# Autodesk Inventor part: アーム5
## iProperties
Created: 2008-02
Part Number: アーム5
Document SubType Name: Modeling
Designer: y-shimazaki
Density: 1 g/cm^3
Author: y-shimazaki
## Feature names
1. 押し出し1 [Extrusion]
2. 押し出し2 [Extrusion]
3. 押し出し3 [Extrusion]
4. フィレット1 [Fillet]
